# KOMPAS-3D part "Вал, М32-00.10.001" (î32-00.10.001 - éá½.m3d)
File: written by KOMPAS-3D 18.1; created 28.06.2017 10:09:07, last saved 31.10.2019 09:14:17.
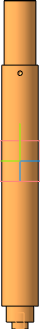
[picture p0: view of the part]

Document properties: Автор: Милов; Организация: Милов; Полное имя файла: D:\Magna\Магна Ins\Магна ins 32\М32-00.10.001 - Вал.m3d

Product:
- Part/product: Вал  | designation М32-00.10.001  | pos. 0
    Масса: 1.30054
    Раздел спецификации: Детали
    Форматы листов документа: A3
    source file: М32-00.10.001 - Вал.cdw

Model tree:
1. Эскиз:1
2. Операция выдавливания:1
     Расстояние 1 = 396
3. Эскиз:12  (with: Операция выдавливания:1)
4. Операция выдавливания:2
     Расстояние 1 = 8.5
5. Эскиз:2  (with: Операция выдавливания:2, Операция выдавливания:1)
6. Отверстие:1  (with: Операция выдавливания:2)  (labels: M10)
     Глубина выреза = 23; Диаметр отверстия = 8.3762; Угол конуса торца = 118
7. M10  (with: Отверстие:1, Операция выдавливания:2)  (labels: cil0_24705-2004 coarse)
     Длина резьбы = 20; Шаг резьбы = 1.5; Номинальный диаметр резьбы = 10
8. Фаска:1  (with: Отверстие:1)
     Угол = 45; Длина 1 = 1.6; Длина 2 = 1.6
9. Эскиз:3  (with: Операция выдавливания:1)
10. Вырезать элемент выдавливания:1  (with: Операция вращения:1)
11. Отверстие:2  (with: Операция выдавливания:1)
     Глубина выреза = 52; Диаметр отверстия = 24; Угол конуса торца = 118
12. Эскиз:7  (with: Операция выдавливания:1, Отверстие:2)
13. Вырезать элемент выдавливания:4
     Расстояние 1 = 80
14. Фаска:4  (with: Вырезать элемент выдавливания:4)
     Угол = 45; Длина 1 = 1; Длина 2 = 1
15. Эскиз:9  (with: Вырезать элемент выдавливания:4)
16. Вырезать элемент выдавливания:6
     Расстояние 1 = 14
17. Эскиз:13  (with: Операция выдавливания:1, Операция выдавливания:2)
18. Отверстие:3  (with: Операция выдавливания:1)
     Глубина выреза = 10; Диаметр отверстия = 7; Угол конуса торца = 118; Расстояние 1 = -13
19. Массив по концентрической сетке:1  (with: Отверстие:3, Эскиз:13)  (4 pattern instances)
     Шаг 2 = 360
20. Эскиз:15  (with: Вырезать элемент выдавливания:1)
21. Вырезать элемент выдавливания:8
     Расстояние 1 = 50
22. Смещенная плоскость:2
     Расстояние = 24
23. Эскиз:17  (with: Отверстие:2)
24. Отверстие:4
     Глубина выреза = 8; Диаметр отверстия = 6; Угол конуса торца = 118; Координата Y = -108
25. Смещенная плоскость:1  (with: Вырезать элемент выдавливания:8)
     Расстояние = 13
26. Эскиз:16  (with: Вырезать элемент выдавливания:8)
27. Вырезать элемент выдавливания:9
     Расстояние 1 = 4
28. Фаска:5  (with: Вырезать элемент выдавливания:9)
     Угол = 45; Длина 1 = 1; Длина 2 = 1
29. Эскиз:19  (with: Операция выдавливания:2)
30. Вырезать элемент выдавливания:11  (with: Операция выдавливания:1)
     Расстояние 1 = 8.5
31. Элемент выдавливания:2  (with: Вырезать элемент выдавливания:1)
     Расстояние 1 = 0.2

Referenced files in D:\Magna\Магна Ins\Магна ins 32\: М32-00.00.000 - Магна Ins 32-L-3(1)-N.a3d
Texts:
  Втулка / скольжения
